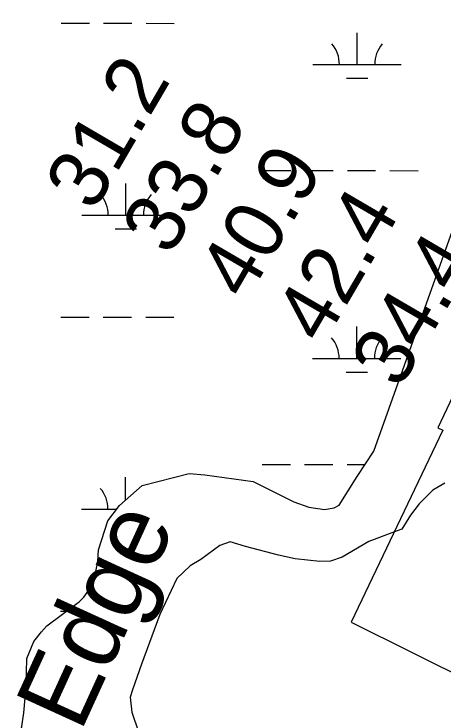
# Model space of a CAD drawing. Extents: x 3148686 to 3186545, y 916144 to 941516.
# Drawn here: x 3158112 to 3158599, y 926690 to 927482 of the extents above; entities that cross this region are included whole.
import ezdxf

# ---------------------------------------------------------------- set-up
doc = ezdxf.new("R2010")
doc.units = 0
for name, color, linetype in [('V-RIVR-EDGE', 7, 'Continuous'), ('V-RIVR-IDEN', 7, 'Continuous'), ('V-RIVR-RANG', 7, 'Continuous'), ('V-RRAP-RVMT', 7, 'Continuous'), ('V-SITE-VEGE', 7, 'Continuous'), ('V-WETL-SWMP', 7, 'Continuous')]:
    doc.layers.add(name, color=color, linetype=linetype)

msp = doc.modelspace()

# ---------------------------------------------------------------- linework, layer by layer
at = {"layer": 'V-RIVR-EDGE'}
msp.add_lwpolyline([(3158599.59, 926950.97), (3158586.1, 926942.85), (3158570.46, 926927.64), (3158560.85, 926914.9), (3158550.89, 926898.96), (3158542.72, 926895.79), (3158513.62, 926884.87), (3158483.44, 926867.22), (3158470.3, 926862.64), (3158458.25, 926862.32), (3158430.24, 926865.22), (3158411.46, 926869.52), (3158373.9, 926879.19), (3158356.53, 926884.55), (3158345.18, 926880.33), (3158323.51, 926864.42), (3158311.43, 926857.36), (3158296.51, 926843.21), (3158277.26, 926802.13), (3158256.55, 926746.15), (3158246.2, 926717.1), (3158243.69, 926708.6), (3158245.42, 926691.57), (3158253.17, 926669.57)], dxfattribs=at)
at = {"layer": 'V-RRAP-RVMT'}
for points in [[(3159294.66, 928840.54), (3159192.83, 928570.83), (3159198.43, 928568.55), (3159146.94, 928433.56), (3159098.63, 928321.7), (3159090.5, 928325.75), (3159027.44, 928176.64), (3159041.68, 928169.55), (3158985.75, 928024.49), (3158991.85, 928021.83), (3158839.43, 927628.02), (3158847.82, 927624.35), (3158746.69, 927389.79), (3158750.63, 927387.95), (3158705.95, 927292.4), (3158714.21, 927288.22), (3158630.37, 927109.98), (3158635.84, 927106.87), (3158591.54, 927013.73), (3158597.19, 927010.94), (3158493.53, 926793.78)], [(3158493.53, 926793.78), (3158702.13, 926689.96), (3158769.5, 926826.84), (3158765.94, 926828.8), (3158807.63, 926916.75), (3158799.75, 926920.77), (3158842.46, 927010.72), (3158833.82, 927015.28), (3159013.75, 927398.86), (3159002.88, 927404.24), (3159062.95, 927543.81), (3159050.62, 927550.15), (3159153.45, 927816.87), (3159168.07, 927811.55), (3159214.21, 927936.64), (3159219.43, 927934.61), (3159271.54, 928074.78), (3159287.69, 928068.45), (3159343.74, 928202.79), (3159353.02, 928199.49), (3159460.3, 928473.43), (3159488.78, 928462.79), (3159592.76, 928741.98)]]:
    msp.add_lwpolyline(points, dxfattribs=at)
at = {"layer": 'V-SITE-VEGE'}
for p, q in [((3158588.51, 927182), (3158682.55, 927445.66)), ((3158519.28, 926987.24), (3158588.51, 927182)), ((3158500.49, 926958.5), (3158519.28, 926987.24)), ((3158257.19, 926948.42), (3158310.14, 926962.03)), ((3158310.14, 926962.03), (3158327.89, 926960.33)), ((3158327.89, 926960.33), (3158382.58, 926952.78)), ((3158382.58, 926952.78), (3158428.88, 926929.66)), ((3158479.91, 926926.12), (3158500.49, 926958.5)), ((3158231.32, 926925.49), (3158257.19, 926948.42)), ((3158428.88, 926929.66), (3158445.65, 926923.71)), ((3158218.11, 926908.48), (3158231.32, 926925.49)), ((3158445.65, 926923.71), (3158463.41, 926920.99)), ((3158463.41, 926920.99), (3158474.28, 926922.87)), ((3158474.28, 926922.87), (3158479.91, 926926.12)), ((3158207.61, 926875.55), (3158218.11, 926908.48)), ((3158206.89, 926862.24), (3158207.61, 926875.55)), ((3158203.56, 926845.29), (3158206.89, 926862.24)), ((3158197.79, 926831.34), (3158203.56, 926845.29)), ((3158190.99, 926822.03), (3158197.79, 926831.34)), ((3158149.44, 926789.33), (3158186.18, 926816.96)), ((3158186.18, 926816.96), (3158190.99, 926822.03)), ((3158143.43, 926782.84), (3158149.44, 926789.33)), ((3158134.42, 926771.9), (3158143.43, 926782.84)), ((3158126.47, 926752.5), (3158134.42, 926771.9)), ((3158125.85, 926720.84), (3158126.47, 926752.5)), ((3158123.4, 926690.98), (3158125.85, 926720.84)), ((3158112.13, 926616.72), (3158123.4, 926690.98))]:
    msp.add_line(p, q, dxfattribs=at)
at = {"layer": 'V-WETL-SWMP'}
for p, q in [((3158165.51, 927471.56), (3158197.51, 927471.52)), ((3158213.51, 927471.51), (3158245.51, 927471.47)), ((3158261.51, 927471.46), (3158293.51, 927471.42)), ((3158500.3, 927424.77), (3158500.34, 927460.77)), ((3158450.3, 927424.83), (3158550.3, 927424.72)), ((3158488.29, 927409.36), (3158512.29, 927409.33)), ((3158393.33, 927304.82), (3158425.33, 927304.78)), ((3158441.33, 927304.77), (3158473.33, 927304.73)), ((3158489.33, 927304.71), (3158521.33, 927304.68)), ((3158537.33, 927304.66), (3158569.33, 927304.63)), ((3158238.69, 927254.24), (3158238.73, 927290.24)), ((3158188.69, 927254.29), (3158288.69, 927254.18)), ((3158226.67, 927238.82), (3158250.67, 927238.79)), ((3158165.16, 927138.88), (3158197.16, 927138.85)), ((3158213.16, 927138.83), (3158245.16, 927138.8)), ((3158261.16, 927138.78), (3158293.16, 927138.75)), ((3158499.95, 927092.1), (3158499.99, 927128.1)), ((3158449.95, 927092.15), (3158549.95, 927092.05)), ((3158487.94, 927076.68), (3158511.94, 927076.66)), ((3158392.98, 926972.14), (3158424.98, 926972.11)), ((3158440.98, 926972.09), (3158472.98, 926972.06)), ((3158488.98, 926972.04), (3158509.33, 926972.02)), ((3158238.35, 926931.72), (3158238.37, 926957.56)), ((3158188.34, 926921.61), (3158228.28, 926921.57)), ((3158164.81, 926806.21), (3158171.87, 926806.2))]:
    msp.add_line(p, q, dxfattribs=at)
msp.add_lwpolyline([(3158112.13, 926616.72), (3158123.4, 926690.99), (3158125.85, 926720.84), (3158126.47, 926752.5), (3158134.42, 926771.9), (3158143.43, 926782.84), (3158149.44, 926789.33), (3158186.18, 926816.96), (3158190.99, 926822.03), (3158197.79, 926831.34), (3158203.56, 926845.29), (3158206.89, 926862.24), (3158207.61, 926875.55), (3158218.11, 926908.48), (3158231.32, 926925.49), (3158257.19, 926948.42), (3158310.14, 926962.04), (3158327.89, 926960.33), (3158382.58, 926952.78), (3158428.88, 926929.66), (3158445.65, 926923.71), (3158463.41, 926920.99), (3158474.28, 926922.87), (3158479.91, 926926.12), (3158500.49, 926958.5), (3158519.28, 926987.24), (3158588.51, 927182), (3158682.55, 927445.66)], dxfattribs=at)
for centre, start, end in [((3158445.06, 927425.31), 359.16781, 40.71147), ((3158555.55, 927425.19), 139.1678, 180.71146), ((3158183.44, 927254.77), 359.16781, 40.71147), ((3158293.93, 927254.65), 139.1678, 180.71146), ((3158444.71, 927092.63), 359.16781, 40.71147), ((3158555.2, 927092.52), 139.1678, 180.71146), ((3158183.09, 926922.09), 359.16781, 40.71147)]:
    msp.add_arc(centre, 35.25, start, end, dxfattribs=at)

# ---------------------------------------------------------------- texts
at = {"layer": 'V-RIVR-IDEN'}
msp.add_text('Edge', height=83, rotation=65.47074, dxfattribs=at).set_placement((3158187.34, 926667.83))
at = {"layer": 'V-RIVR-RANG'}
for s, p in [('31.2', (3158202.23, 927256.82)), ('33.8', (3158288.71, 927206.6)), ('40.9', (3158375.05, 927156.16)), ('42.4', (3158461.66, 927106.17)), ('34.4', (3158548.14, 927055.95))]:
    msp.add_text(s, height=67, rotation=59.71833, dxfattribs=at).set_placement(p)

doc.saveas('drawing.dxf')
